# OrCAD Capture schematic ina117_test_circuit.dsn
size A; title: INA117: High Common-Mode Voltage Difference Amplifier; rev: 1.0; note: Datasheet: SBOS154A  EVM: N/A
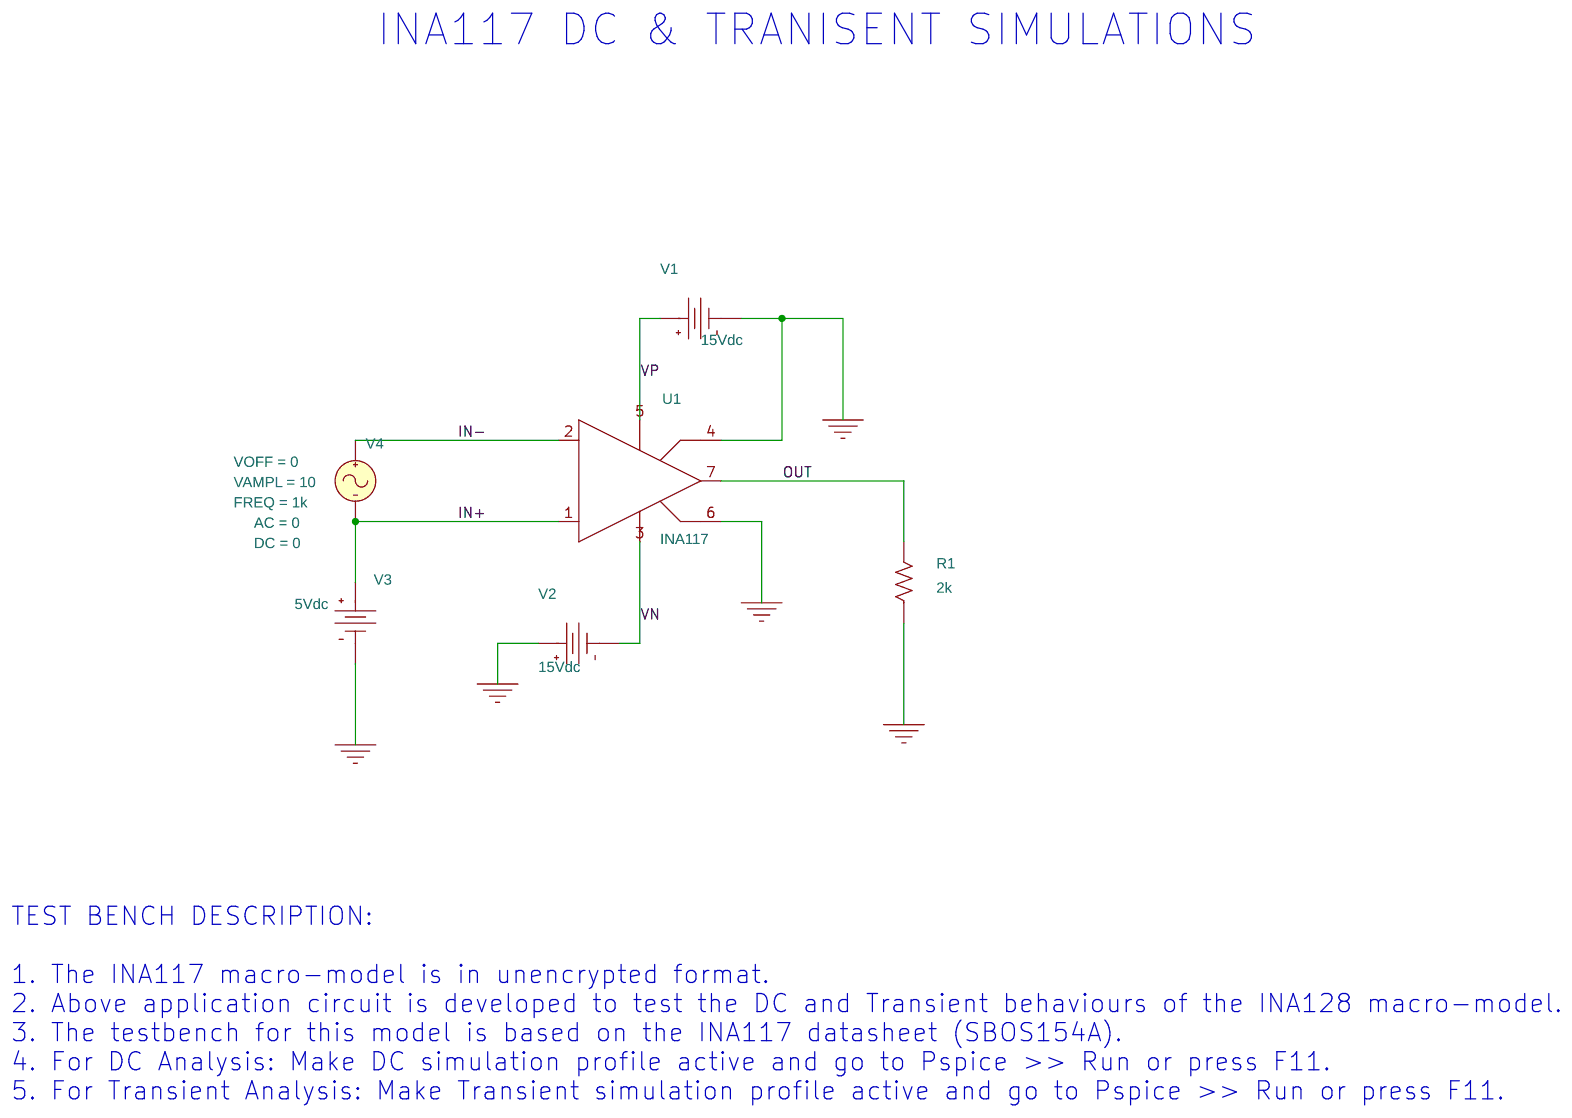
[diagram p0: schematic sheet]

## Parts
R1  2k  [AXRC05]
U1  INA117
V1  VDC
V2  VDC
V3  VDC
V4  VSIN

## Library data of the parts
R1 = R
U1 = INA117
V1 V2 = VDC: DC: 15Vdc
V3 = VDC: DC: 5Vdc
V4 = VSIN: AC: 0; DC: 0; FREQ: 1k; VAMPL: 10; VOFF: 0

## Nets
0: R1.1 U1.4(REFA) U1.6(REFB) V1.1(-) V2.0(+) V3.1(-)
IN+: U1.1(+) V3.0(+) V4.2(-)
IN-: U1.2(-) V4.1(+)
OUT: R1.2 U1.7(OUT)
VN: U1.3(V-) V2.1(-)
VP: U1.5(V+) V1.0(+)

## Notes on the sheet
- INA117 DC & TRANISENT SIMULATIONS
- TEST BENCH DESCRIPTION:
  1. The INA117 macro-model is in unencrypted format.
  2. Above application circuit is developed to test the DC and Transient behaviours of the INA128 macro-model.
  3. The testbench for this model is based on the INA117 datasheet (SBOS154A).
  4. For DC Analysis: Make DC simulation profile active and go to Pspice >> Run or press F11.
  5. For Transient Analysis: Make Transient simulation profile active and go to Pspice >> Run or press F11.
